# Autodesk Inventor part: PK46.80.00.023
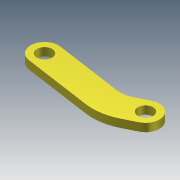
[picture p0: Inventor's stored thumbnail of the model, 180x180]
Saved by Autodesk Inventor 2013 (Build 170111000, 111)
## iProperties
Created: 2005-04
Part Number: PK46.80.00.023
Material: Steel, Mild
Document SubType Name: Modeling
Designer: salex
Manufacturer: Standard
Standards Organization: Custom
Density: 7.86 g/cm^3
Mass: 1542.86 g
Surface Area: 368.91 cm^2
Volume: 196.292 cm^3
Author: salex
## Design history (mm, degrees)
sketch "Эскиз5"
  geometry: L1 (3.953, 27.214)-(134.626, 8.233); L2 (163.933, 12.873)-(187.835, 24.663); L3 (-3.953, -27.214)-(128.257, -46.419); L4 (186.87, -37.14)-(212.165, -24.663); C1 r 15 at (0, 0); C2 r 15 at (200, 0); A1 r 27.5 centre (0, 0) between (3.953, 27.214) and (-3.953, -27.214); A2 r 27.5 centre (200, 0) between (212.165, -24.663) and (187.835, 24.663); A3 r 50 centre (141.813, 57.714) between (134.626, 8.233) and (163.933, 12.873); A4 r 100 centre (142.632, 52.543) between (128.257, -46.419) and (186.87, -37.14); 1 further point
  constraints: 8 end point, 8 point on circle, 8 tangent, 6 centre point, 2 coincident, 2 equal radius, 2 parallel, 2 point on line, 1 other
  dimensions: "d29" = 30 diameter of C1; "d30" = 0 vertical distance of C2.centre C1.centre; "d31" = 200 distance of C2.centre C1.centre; "d32" = 6 vertical distance of point (150, 6) C1.centre; "d33" = 27.5 radius of A1; "d34" = 150 horizontal distance of point (150, 6) C1.centre; "d35" = 50 radius of A3; "d36" = 100 radius of A4
extrude "Выдавливание5" new body sketch "Эскиз5" distance "d37" = 16; taper "d38" = 0 deg
body "Solid1"
